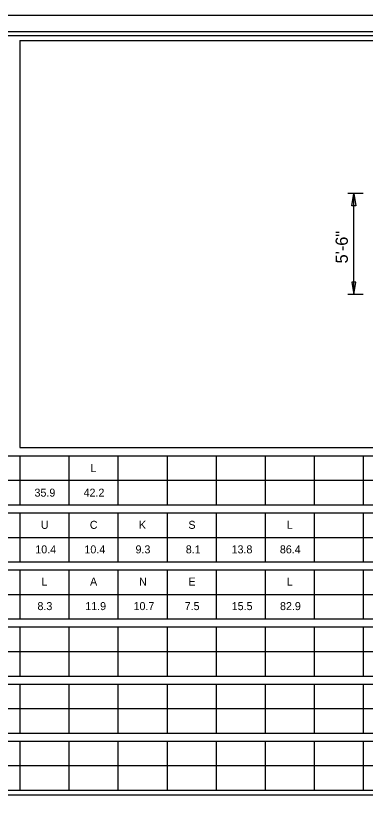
# Model space of a CAD drawing. Extents: x 17890628 to 17890844, y 17897506 to 17897992.
# Drawn here: x 17890726.2 to 17890745.27, y 17897557.55 to 17897600.12 of the extents above; entities that cross this region are included whole.
import ezdxf

# ---------------------------------------------------------------- set-up
doc = ezdxf.new("R2010")
doc.units = 0
for name, color, linetype in [('GSDims', 7, 'Continuous'), ('GSSign', 7, 'Continuous'), ('PlotBorder_dp', 7, 'Continuous'), ('SheetBorder_dp', 7, 'Continuous'), ('SheetLinesMisc2_dp', 7, 'Continuous')]:
    doc.layers.add(name, color=color, linetype=linetype)

msp = doc.modelspace()

# ---------------------------------------------------------------- linework, layer by layer
at = {"layer": 'GSDims'}
for p, q in [((17890745.146, 17897590.427), (17890744.312, 17897590.427)), ((17890744.646, 17897584.934), (17890744.646, 17897590.427)), ((17890745.146, 17897584.934), (17890744.312, 17897584.934))]:
    msp.add_line(p, q, dxfattribs=at)
for points in [[(17890744.646, 17897590.427), (17890744.757, 17897589.761), (17890744.534, 17897589.761)], [(17890744.646, 17897584.934), (17890744.757, 17897585.6), (17890744.534, 17897585.6)]]:
    msp.add_lwpolyline(points, close=True, dxfattribs=at)
at = {"layer": 'PlotBorder_dp'}
msp.add_lwpolyline([(17890700.471, 17897507.81), (17890844.155, 17897507.81), (17890844.155, 17897600.116), (17890700.471, 17897600.116)], close=True, dxfattribs=at)
at = {"layer": 'SheetBorder_dp'}
msp.add_line((17890705.26, 17897599.245), (17890839.365, 17897599.245), dxfattribs=at)
at = {"layer": 'SheetLinesMisc2_dp'}
for p, q in [((17890705.5, 17897599.039), (17890839.233, 17897599.039)), ((17890726.429, 17897598.762), (17890771.912, 17897598.762)), ((17890726.429, 17897598.762), (17890726.429, 17897576.606)), ((17890726.429, 17897576.606), (17890771.912, 17897576.606)), ((17890706.142, 17897576.15), (17890771.912, 17897576.15)), ((17890726.429, 17897576.15), (17890726.429, 17897573.478)), ((17890729.104, 17897576.15), (17890729.104, 17897573.478)), ((17890731.779, 17897576.15), (17890731.779, 17897573.478)), ((17890734.455, 17897576.15), (17890734.455, 17897573.478)), ((17890737.131, 17897576.15), (17890737.131, 17897573.478)), ((17890739.806, 17897576.15), (17890739.806, 17897573.478)), ((17890742.481, 17897576.15), (17890742.481, 17897573.478)), ((17890745.157, 17897576.15), (17890745.157, 17897573.478)), ((17890706.142, 17897574.814), (17890771.912, 17897574.814)), ((17890706.142, 17897573.478), (17890771.912, 17897573.478)), ((17890706.142, 17897573.042), (17890771.912, 17897573.042)), ((17890726.429, 17897573.042), (17890726.429, 17897570.37)), ((17890729.104, 17897573.042), (17890729.104, 17897570.37)), ((17890731.779, 17897573.042), (17890731.779, 17897570.37)), ((17890734.455, 17897573.042), (17890734.455, 17897570.37)), ((17890737.131, 17897573.042), (17890737.131, 17897570.37)), ((17890739.806, 17897573.042), (17890739.806, 17897570.37)), ((17890742.481, 17897573.042), (17890742.481, 17897570.37)), ((17890745.157, 17897573.042), (17890745.157, 17897570.37)), ((17890706.142, 17897571.706), (17890771.912, 17897571.706)), ((17890706.142, 17897570.37), (17890771.912, 17897570.37)), ((17890706.142, 17897569.935), (17890771.912, 17897569.935)), ((17890726.429, 17897569.935), (17890726.429, 17897567.263)), ((17890729.104, 17897569.935), (17890729.104, 17897567.263)), ((17890731.779, 17897569.935), (17890731.779, 17897567.263)), ((17890734.455, 17897569.935), (17890734.455, 17897567.263)), ((17890737.131, 17897569.935), (17890737.131, 17897567.263)), ((17890739.806, 17897569.935), (17890739.806, 17897567.263)), ((17890742.481, 17897569.935), (17890742.481, 17897567.263)), ((17890745.157, 17897569.935), (17890745.157, 17897567.263)), ((17890706.142, 17897568.598), (17890771.912, 17897568.598)), ((17890706.142, 17897567.263), (17890771.912, 17897567.263)), ((17890706.142, 17897566.827), (17890771.912, 17897566.827)), ((17890726.429, 17897566.827), (17890726.429, 17897564.154)), ((17890729.104, 17897566.827), (17890729.104, 17897564.154)), ((17890731.779, 17897566.827), (17890731.779, 17897564.154)), ((17890734.455, 17897566.827), (17890734.455, 17897564.154)), ((17890737.131, 17897566.827), (17890737.131, 17897564.154)), ((17890739.806, 17897566.827), (17890739.806, 17897564.154)), ((17890742.481, 17897566.827), (17890742.481, 17897564.154)), ((17890745.157, 17897566.827), (17890745.157, 17897564.154)), ((17890706.142, 17897565.49), (17890771.912, 17897565.49)), ((17890706.142, 17897564.154), (17890771.912, 17897564.154)), ((17890706.142, 17897563.719), (17890771.912, 17897563.719)), ((17890726.429, 17897563.719), (17890726.429, 17897561.047)), ((17890729.104, 17897563.719), (17890729.104, 17897561.047)), ((17890731.779, 17897563.719), (17890731.779, 17897561.047)), ((17890734.455, 17897563.719), (17890734.455, 17897561.047)), ((17890737.131, 17897563.719), (17890737.131, 17897561.047)), ((17890739.806, 17897563.719), (17890739.806, 17897561.047)), ((17890742.481, 17897563.719), (17890742.481, 17897561.047)), ((17890745.157, 17897563.719), (17890745.157, 17897561.047)), ((17890706.142, 17897562.383), (17890771.912, 17897562.383)), ((17890706.142, 17897561.047), (17890771.912, 17897561.047)), ((17890706.142, 17897560.611), (17890771.912, 17897560.611)), ((17890726.429, 17897560.611), (17890726.429, 17897557.939)), ((17890729.104, 17897560.611), (17890729.104, 17897557.939)), ((17890731.779, 17897560.611), (17890731.779, 17897557.939)), ((17890734.455, 17897560.611), (17890734.455, 17897557.939)), ((17890737.131, 17897560.611), (17890737.131, 17897557.939)), ((17890739.806, 17897560.611), (17890739.806, 17897557.939)), ((17890742.481, 17897560.611), (17890742.481, 17897557.939)), ((17890745.157, 17897560.611), (17890745.157, 17897557.939)), ((17890706.142, 17897559.276), (17890771.912, 17897559.276)), ((17890705.5, 17897557.675), (17890839.233, 17897557.675)), ((17890706.142, 17897557.939), (17890771.912, 17897557.939))]:
    msp.add_line(p, q, dxfattribs=at)

# ---------------------------------------------------------------- texts
at = {"layer": 'GSDims'}
msp.add_text('5\'-6"', height=0.6667, rotation=90, dxfattribs=at).set_placement((17890744.312, 17897586.621))
at = {"layer": 'GSSign'}
for s, height, p in [('L', 0.436, (17890730.28, 17897575.258)), ('35.9', 0.4357, (17890727.231, 17897573.922)), ('42.2', 0.4357, (17890729.907, 17897573.922)), ('U', 0.436, (17890727.578, 17897572.169)), ('C', 0.436, (17890730.246, 17897572.169)), ('K', 0.436, (17890732.925, 17897572.169)), ('S', 0.436, (17890735.622, 17897572.169)), ('L', 0.436, (17890740.985, 17897572.169)), ('10.4', 0.4357, (17890727.275, 17897570.832)), ('10.4', 0.4357, (17890729.951, 17897570.832)), ('9.3', 0.4357, (17890732.738, 17897570.832)), ('8.1', 0.4357, (17890735.479, 17897570.832)), ('13.8', 0.4357, (17890737.976, 17897570.832)), ('86.4', 0.4357, (17890740.609, 17897570.832)), ('L', 0.436, (17890727.613, 17897569.079)), ('A', 0.436, (17890730.258, 17897569.079)), ('N', 0.436, (17890732.932, 17897569.079)), ('E', 0.436, (17890735.625, 17897569.079)), ('L', 0.436, (17890740.989, 17897569.079)), ('8.3', 0.4357, (17890727.392, 17897567.743)), ('11.9', 0.4357, (17890729.998, 17897567.743)), ('10.7', 0.4357, (17890732.63, 17897567.743)), ('7.5', 0.4357, (17890735.418, 17897567.743)), ('15.5', 0.4357, (17890737.983, 17897567.743)), ('82.9', 0.4357, (17890740.616, 17897567.743))]:
    msp.add_text(s, height=height, dxfattribs=at).set_placement(p)

doc.saveas('drawing.dxf')
